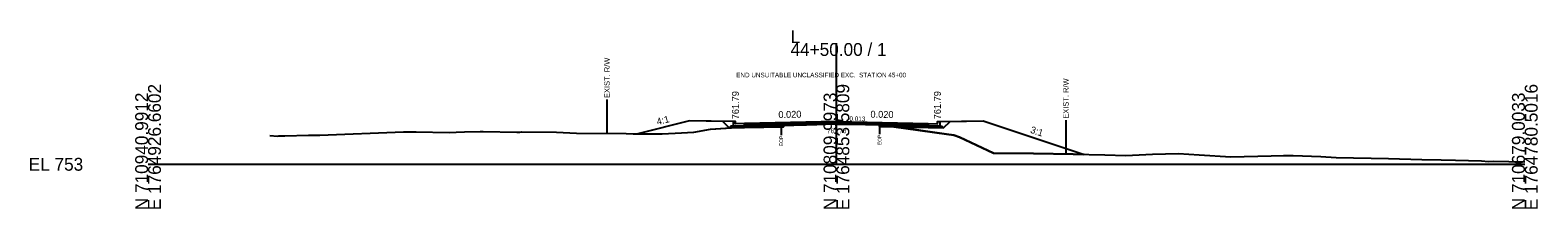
# Model space of a CAD drawing. Extents: x -26 to 5303, y -10 to 9578.
# Drawn here: x 2974.3 to 3302.8, y 4490.3 to 4529.2 of the extents above; entities that cross this region are included whole.
import ezdxf

# ---------------------------------------------------------------- set-up
doc = ezdxf.new("R2010")
doc.units = 0
for name, color, linetype in [('Default', 7, 'Continuous'), ('Exist CMT Pavement', 7, 'Continuous'), ('Exist Cross Section Cell', 7, 'Continuous'), ('Exist XS Ground Line', 7, 'Continuous'), ('Old_Level_10', 7, 'Continuous'), ('Old_Level_3', 7, 'Continuous'), ('Old_Level_4', 7, 'Continuous'), ('Prop CMT Conc Surface', 7, 'Continuous'), ('Prop CMT Concrete Structures', 7, 'Continuous'), ('Prop CMT Pvmt Course 1', 7, 'Continuous'), ('Prop CMT Pvmt Course 1 CG', 7, 'Continuous'), ('Prop CMT Pvmt Course 2', 7, 'Continuous'), ('Prop CMT Pvmt Course 3', 7, 'Continuous'), ('Prop CMT Pvmt Surface', 7, 'Continuous'), ('Prop CMT Slope Grass', 7, 'Continuous'), ('Prop CMT Subgrade Earthwork', 7, 'Continuous'), ('Prop XS Earthwork Shape', 7, 'Continuous'), ('Prop XS Hydro Elevations', 7, 'Continuous'), ('Prop XS SE Text', 7, 'Continuous'), ('Prop XS Side Slope Text', 7, 'Continuous'), ('Prop XS Wedging', 7, 'Continuous'), ('Scratch_Level_5', 7, 'Continuous')]:
    doc.layers.add(name, color=color, linetype=linetype)

msp = doc.modelspace()

# ---------------------------------------------------------------- linework, layer by layer
at = {"layer": 'Exist CMT Pavement'}
msp.add_lwpolyline([(3138.48, 4508.46), (3138.9, 4508.48), (3139.98, 4508.51), (3140.72, 4508.54), (3142.84, 4508.61), (3143.44, 4508.62), (3144.52, 4508.66), (3145.28, 4508.68), (3145.7, 4508.69), (3147.12, 4508.73), (3147.68, 4508.75), (3148.5, 4508.79), (3149.17, 4508.8), (3150, 4508.76), (3150.79, 4508.74), (3151.43, 4508.73), (3152.63, 4508.72), (3154.29, 4508.71), (3154.78, 4508.71), (3156.31, 4508.68), (3157.15, 4508.66), (3158.24, 4508.64), (3158.97, 4508.63), (3159.4, 4508.62)], dxfattribs=at)
at = {"layer": 'Exist Cross Section Cell'}
for p, q in [((3150, 4500), (3150, 4526.39)), ((3000, 4500), (3150, 4500)), ((3150, 4500), (3300, 4500))]:
    msp.add_line(p, q, dxfattribs=at)
at = {"layer": 'Exist XS Ground Line'}
msp.add_lwpolyline([(3026.57, 4506.26), (3028.17, 4506.14), (3028.49, 4506.17), (3029.82, 4506.22), (3034.99, 4506.33), (3037.43, 4506.34), (3055.66, 4507.07), (3058.45, 4507.07), (3065.62, 4506.92), (3067.13, 4506.97), (3068.92, 4507.03), (3072.36, 4507.13), (3073.02, 4507.11), (3080.39, 4506.99), (3081.03, 4507.02), (3081.39, 4507.06), (3088.97, 4507.02), (3093.37, 4506.77), (3104.2, 4506.68), (3105.72, 4506.66), (3112, 4506.65), (3113.39, 4506.72), (3114.85, 4506.79), (3118.9, 4506.96), (3122.57, 4507.65), (3135.73, 4508.48), (3137.34, 4508.47), (3137.97, 4508.38), (3138.48, 4508.46), (3138.9, 4508.48), (3139.98, 4508.51), (3140.72, 4508.54), (3142.84, 4508.61), (3144.52, 4508.66), (3145.7, 4508.69), (3147.12, 4508.73), (3147.68, 4508.75), (3148.16, 4508.77), (3148.5, 4508.79), (3149.17, 4508.8), (3150, 4508.76), (3150.79, 4508.74), (3151.43, 4508.73), (3153.67, 4508.72), (3154.47, 4508.71), (3154.78, 4508.71), (3156.31, 4508.68), (3157.15, 4508.66), (3158.24, 4508.64), (3158.97, 4508.63), (3159.4, 4508.62), (3174, 4506.59), (3175.61, 4506.36), (3176.84, 4505.89), (3184.26, 4502.43), (3192.96, 4502.35), (3201.61, 4502.17), (3208.48, 4502.06), (3213.06, 4501.92), (3218.84, 4502.17), (3224.51, 4502.32), (3229.01, 4502.05), (3235.96, 4501.61), (3244.74, 4501.86), (3247.41, 4501.89), (3249.54, 4501.91), (3255.53, 4501.72), (3258.87, 4501.5), (3270.32, 4501.28), (3277.58, 4501.04), (3281.77, 4500.99), (3284.93, 4500.88), (3290.59, 4500.74), (3292.06, 4500.64), (3293.22, 4500.67), (3296.55, 4500.6), (3300, 4500.54)], dxfattribs=at)
at = {"layer": 'Old_Level_10'}
for p, q in [((3100, 4514.11), (3100, 4506.71)), ((3137.97, 4508.38), (3137.97, 4506.33)), ((3159.4, 4508.62), (3159.4, 4506.57)), ((3200, 4509.61), (3200, 4502.21))]:
    msp.add_line(p, q, dxfattribs=at)
at = {"layer": 'Old_Level_4'}
msp.add_line((3150, 4508.76), (3157.15, 4508.66), dxfattribs=at)
at = {"layer": 'Prop CMT Conc Surface'}
for points in [[(3128, 4508.79), (3128, 4509.29), (3127.5, 4509.29)], [(3130, 4508.91), (3128, 4508.79)], [(3170, 4508.91), (3172, 4508.79)], [(3172, 4508.79), (3172, 4509.29), (3172.5, 4509.29)]]:
    msp.add_lwpolyline(points, dxfattribs=at)
at = {"layer": 'Prop CMT Concrete Structures'}
for points in [[(3130, 4508.91), (3128, 4508.79), (3128, 4509.29), (3127.5, 4509.29)], [(3127.5, 4509.29), (3127.5, 4508.28), (3130, 4508.33)], [(3130, 4508.33), (3130, 4508.91)], [(3170, 4508.91), (3172, 4508.79), (3172, 4509.29), (3172.5, 4509.29)], [(3172.5, 4509.29), (3172.5, 4508.28), (3170, 4508.33)], [(3170, 4508.33), (3170, 4508.91)]]:
    msp.add_lwpolyline(points, dxfattribs=at)
at = {"layer": 'Prop CMT Pvmt Course 1'}
for points in [[(3150, 4509.31), (3130, 4508.91)], [(3130, 4508.91), (3130, 4508.66)], [(3130, 4508.66), (3138.48, 4508.83)], [(3138.48, 4508.83), (3150, 4509.06)], [(3138.48, 4508.83), (3138.48, 4508.83)], [(3150, 4509.06), (3150, 4509.31)], [(3150, 4509.31), (3170, 4508.91)], [(3150, 4509.06), (3150, 4509.06), (3150, 4509.06)], [(3159.4, 4508.87), (3150, 4509.06)], [(3170, 4508.66), (3159.4, 4508.87)], [(3159.4, 4508.87), (3159.4, 4508.87)], [(3170, 4508.91), (3170, 4508.66)]]:
    msp.add_lwpolyline(points, dxfattribs=at)
at = {"layer": 'Prop CMT Pvmt Course 1 CG'}
for points in [[(3130, 4508.33), (3127, 4508.27), (3126.66, 4507.93)], [(3126.66, 4507.93), (3130, 4507.99)], [(3130, 4507.99), (3130, 4508.33)], [(3170, 4508.33), (3173, 4508.27), (3173.34, 4507.93)], [(3170, 4507.99), (3170, 4508.33)], [(3173.34, 4507.93), (3170, 4507.99)]]:
    msp.add_lwpolyline(points, dxfattribs=at)
at = {"layer": 'Prop CMT Pvmt Course 2'}
for points in [[(3138.48, 4508.83), (3130, 4508.66)], [(3130, 4508.66), (3130, 4508.33)], [(3130, 4508.33), (3138.48, 4508.5)], [(3138.48, 4508.5), (3138.48, 4508.83)], [(3159.4, 4508.54), (3159.4, 4508.87)], [(3159.4, 4508.87), (3170, 4508.66)], [(3170, 4508.33), (3159.4, 4508.54)], [(3170, 4508.66), (3170, 4508.33)]]:
    msp.add_lwpolyline(points, dxfattribs=at)
at = {"layer": 'Prop CMT Pvmt Course 3'}
for points in [[(3138.48, 4508.5), (3130, 4508.33)], [(3130, 4508.33), (3130, 4507.99)], [(3130, 4507.99), (3138.48, 4508.16)], [(3138.48, 4508.16), (3138.48, 4508.5)], [(3159.4, 4508.54), (3170, 4508.33)], [(3159.4, 4508.21), (3159.4, 4508.54)], [(3170, 4507.99), (3159.4, 4508.21)], [(3170, 4508.33), (3170, 4507.99)]]:
    msp.add_lwpolyline(points, dxfattribs=at)
at = {"layer": 'Prop CMT Pvmt Surface'}
for points in [[(3150, 4509.31), (3130, 4508.91)], [(3150, 4509.31), (3170, 4508.91)]]:
    msp.add_lwpolyline(points, dxfattribs=at)
at = {"layer": 'Prop CMT Slope Grass'}
for points in [[(3127.5, 4509.29), (3118, 4509.48), (3106.7, 4506.66)], [(3172.5, 4509.29), (3182, 4509.48), (3204.01, 4502.14)]]:
    msp.add_lwpolyline(points, dxfattribs=at)
at = {"layer": 'Prop CMT Subgrade Earthwork'}
for p, q in [((3138.48, 4508.16), (3138.48, 4508.46)), ((3159.4, 4508.21), (3159.4, 4508.62))]:
    msp.add_line(p, q, dxfattribs=at)
for points in [[(3130, 4507.99), (3126.66, 4507.93), (3125.25, 4509.34)], [(3138.48, 4508.16), (3130, 4507.99)], [(3159.4, 4508.21), (3170, 4507.99)], [(3170, 4507.99), (3173.34, 4507.93), (3174.75, 4509.34)]]:
    msp.add_lwpolyline(points, dxfattribs=at)
at = {"layer": 'Prop XS Earthwork Shape'}
for points in [[(3125.25, 4509.34), (3118, 4509.48), (3106.7, 4506.66), (3112, 4506.65), (3113.39, 4506.72), (3114.85, 4506.79), (3118.9, 4506.96), (3122.57, 4507.65), (3127.15, 4507.94), (3126.66, 4507.93)], [(3113.39, 4506.72), (3114.85, 4506.79), (3118.9, 4506.96), (3122.57, 4507.65), (3127.15, 4507.94), (3126.66, 4507.93), (3125.25, 4509.34), (3118, 4509.48), (3106.7, 4506.66), (3112, 4506.65)], [(3138.48, 4508.16), (3138.48, 4508.46), (3137.97, 4508.38), (3137.34, 4508.47), (3135.73, 4508.48), (3127.15, 4507.94), (3130, 4507.99)], [(3135.73, 4508.48), (3137.34, 4508.47), (3137.97, 4508.38), (3138.48, 4508.46), (3138.48, 4508.16), (3130, 4507.99), (3127.15, 4507.94)], [(3159.4, 4508.62), (3162.89, 4508.14), (3159.4, 4508.21)], [(3159.4, 4508.21), (3162.89, 4508.14), (3159.4, 4508.62)], [(3162.89, 4508.14), (3170, 4507.99), (3173.34, 4507.93), (3174.75, 4509.34), (3182, 4509.48), (3204.01, 4502.14), (3201.61, 4502.17), (3192.96, 4502.35), (3184.26, 4502.43), (3176.84, 4505.89), (3175.61, 4506.36), (3174, 4506.59)], [(3173.34, 4507.93), (3174.75, 4509.34), (3182, 4509.48), (3204.01, 4502.14), (3201.61, 4502.17), (3192.96, 4502.35), (3184.26, 4502.43), (3176.84, 4505.89), (3175.61, 4506.36), (3174, 4506.59), (3162.89, 4508.14), (3170, 4507.99)]]:
    msp.add_lwpolyline(points, close=True, dxfattribs=at)
at = {"layer": 'Prop XS Wedging'}
msp.add_lwpolyline([(3138.48, 4508.46), (3138.48, 4508.83), (3138.9, 4508.84), (3139.98, 4508.86), (3140.72, 4508.88), (3142.84, 4508.92), (3143.44, 4508.93), (3144.52, 4508.95), (3145.28, 4508.97), (3145.7, 4508.98), (3147.12, 4509), (3147.68, 4509.02), (3148.5, 4509.03), (3149.17, 4509.05), (3150, 4509.06), (3150.79, 4509.05), (3151.43, 4509.03), (3152.63, 4509.01), (3154.29, 4508.98), (3154.78, 4508.97), (3156.31, 4508.94), (3157.15, 4508.92), (3158.24, 4508.9), (3158.97, 4508.88), (3159.4, 4508.87), (3159.4, 4508.62), (3158.97, 4508.63), (3158.24, 4508.64), (3157.15, 4508.66), (3156.31, 4508.68), (3154.78, 4508.71), (3154.29, 4508.71), (3152.63, 4508.72), (3151.43, 4508.73), (3150.79, 4508.74), (3150, 4508.76), (3149.17, 4508.8), (3148.5, 4508.79), (3147.68, 4508.75), (3147.12, 4508.73), (3145.7, 4508.69), (3145.28, 4508.68), (3144.52, 4508.66), (3143.44, 4508.62), (3142.84, 4508.61), (3140.72, 4508.54), (3139.98, 4508.51), (3138.9, 4508.48)], close=True, dxfattribs=at)

# ---------------------------------------------------------------- texts
at = {"layer": 'Default'}
msp.add_text('-', height=0.0001, dxfattribs=at).set_placement((3000, 4500))
at = {"layer": 'Exist Cross Section Cell'}
for s, p in [('L', (3140, 4526.39)), ('44+50.00 / 1', (3140, 4523.59)), ('EL 753', (2974, 4498.6))]:
    msp.add_text(s, height=2.8, dxfattribs=at).set_placement(p)
for s, p in [('N 710940.9912', (3000, 4490)), ('E 1764926.6602', (3002.8, 4490)), ('N 710809.9973', (3150, 4490)), ('E 1764853.5809', (3152.8, 4490)), ('N 710679.0033', (3300, 4490)), ('E 1764780.5016', (3302.8, 4490))]:
    msp.add_text(s, height=2.8, rotation=90, dxfattribs=at).set_placement(p)
at = {"layer": 'Old_Level_10'}
for s, height, p in [('EXIST. R/W', 1.181, (3100.59, 4514.42)), ('EXIST. R/W', 1.181, (3200.59, 4509.91)), ('EOP', 0.787, (3138.37, 4503.93)), ('EOP', 0.787, (3159.8, 4504.17))]:
    msp.add_text(s, height=height, rotation=90, dxfattribs=at).set_placement(p)
at = {"layer": 'Old_Level_3'}
msp.add_text('761.76', height=1, dxfattribs=at).set_placement((3147.95, 4506.76))
at = {"layer": 'Old_Level_4'}
msp.add_text('0.013', height=1, rotation=359.2502, dxfattribs=at).set_placement((3152.83, 4509.43))
at = {"layer": 'Prop XS Hydro Elevations'}
for p in [(3128.75, 4509.79), (3172.75, 4509.79)]:
    msp.add_text('761.79', height=1.5, rotation=90, dxfattribs=at).set_placement(p)
at = {"layer": 'Prop XS SE Text'}
for rotation, p in [(1.1458, (3137.36, 4510.06)), (358.8542, (3157.4, 4510.16))]:
    msp.add_text('0.020', height=1.5, rotation=rotation, dxfattribs=at).set_placement(p)
at = {"layer": 'Prop XS Side Slope Text'}
for s, rotation, p in [('4:1', 14.0362, (3111.01, 4508.51)), ('3:1', 341.5651, (3192.12, 4506.9))]:
    msp.add_text(s, height=1.5, rotation=rotation, dxfattribs=at).set_placement(p)
at = {"layer": 'Scratch_Level_5'}
msp.add_text('END UNSUITABLE UNCLASSIFIED EXC.  STATION 45+00', height=1, dxfattribs=at).set_placement((3128.16, 4518.93))

doc.saveas('drawing.dxf')
